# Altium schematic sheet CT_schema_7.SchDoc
size 369 x 243 mm
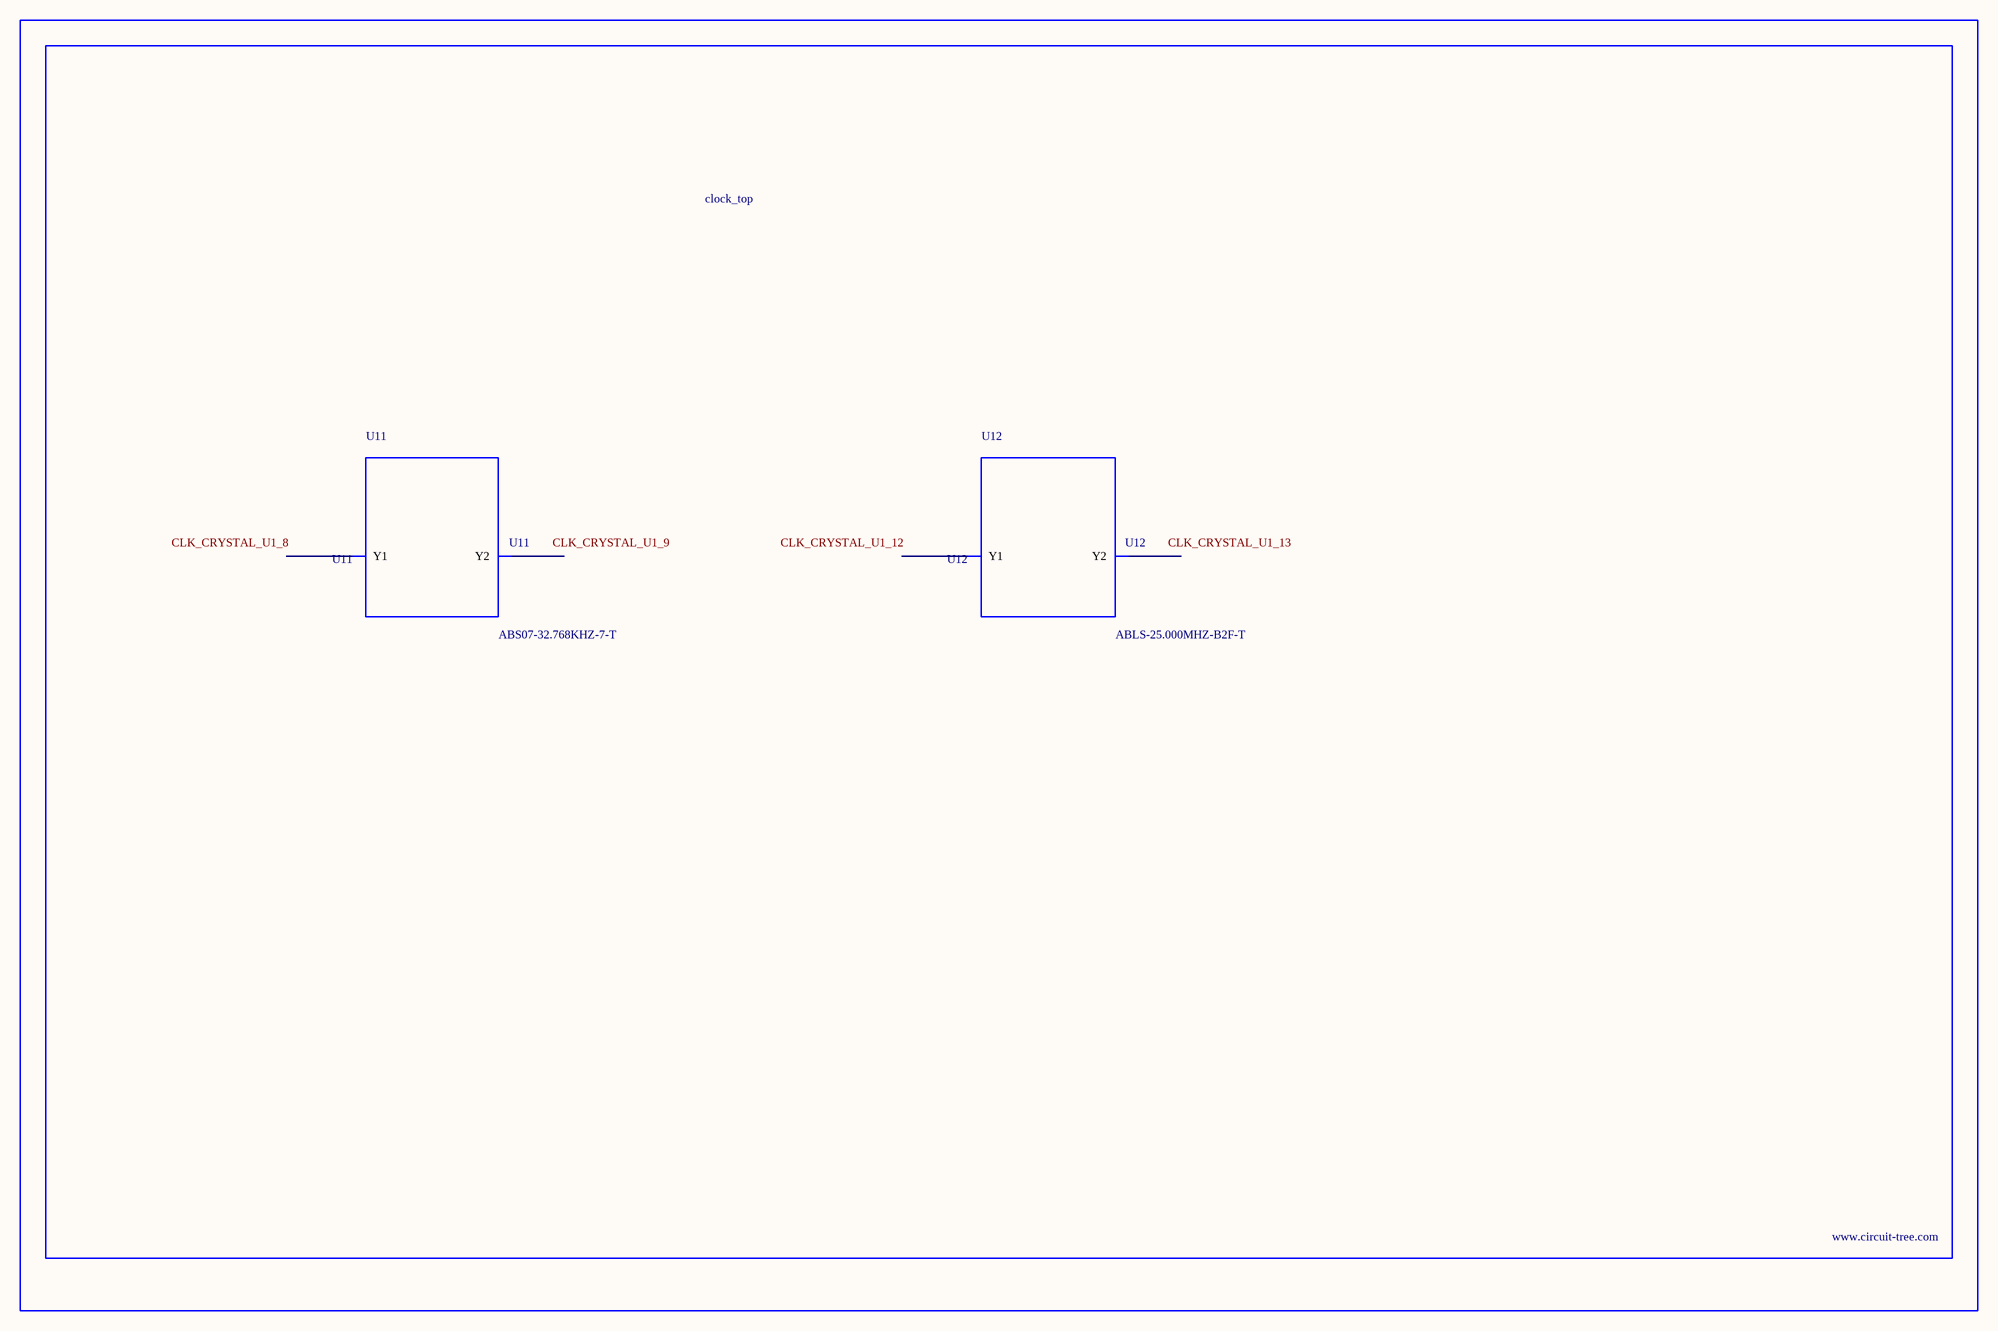
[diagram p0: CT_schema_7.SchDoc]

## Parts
BORDER6  (no value)
U11  ABS07-32.768KHZ-7-T  [ABS07-32.768KHZ-7-T]
U12  ABLS-25.000MHZ-B2F-T  [ABLS-25.000MHZ-B2F-T]

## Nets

Not connected (* = marked no-connect by the designer): U11 1(Y1) 2(Y2); U12 1(Y1) 2(Y2)

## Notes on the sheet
- Labels drawn without touching a wire or pin: CLK_CRYSTAL_U1_8, CLK_CRYSTAL_U1_9, CLK_CRYSTAL_U1_12, CLK_CRYSTAL_U1_13

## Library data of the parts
BORDER6 = BORDER_PAGE6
